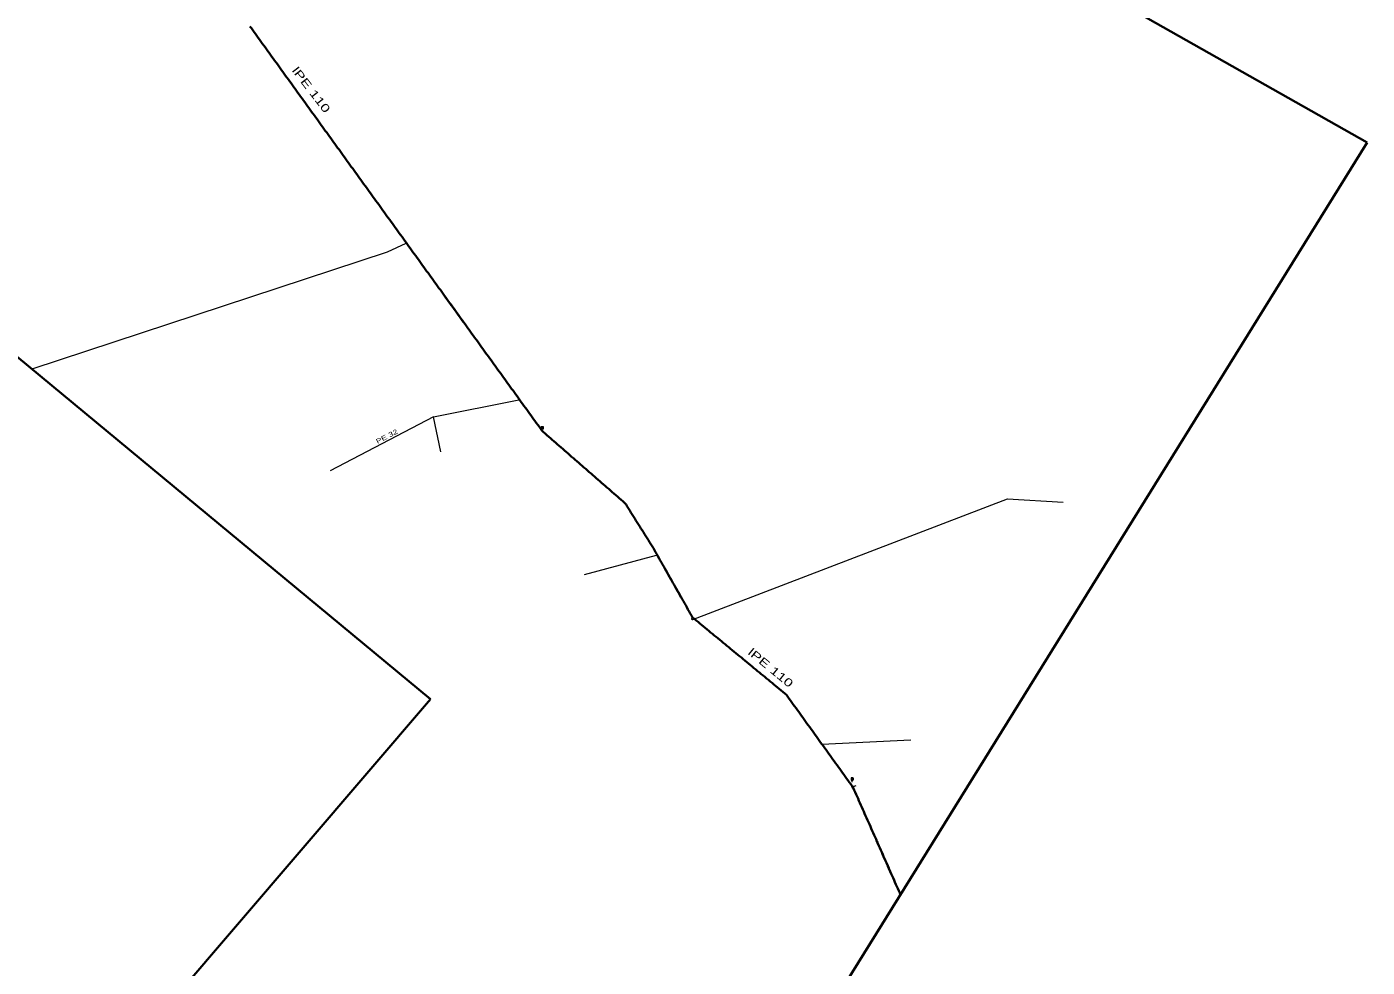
# Model space of a CAD drawing. Extents: x -18.3 to 18.3, y -32.8 to 32.8.
# Drawn here: x 15.245 to 18.281, y 7.625 to 9.754 of the extents above; entities that cross this region are included whole.
import ezdxf

# ---------------------------------------------------------------- set-up
doc = ezdxf.new("R2010")
doc.units = 0
doc.header["$LTSCALE"] = 0.0072
doc.layers.add('16', color=7, linetype='Continuous')
doc.layers.add('18', color=7, linetype='Continuous')
for name, color, linetype, lineweight in [('28', 7, 'Continuous', 13), ('29', 7, 'Continuous', 13), ('5', 7, 'Continuous', 35), ('63', 7, 'Continuous', 35)]:
    doc.layers.add(name, color=color, linetype=linetype, lineweight=lineweight)

msp = doc.modelspace()

# ---------------------------------------------------------------- linework, layer by layer
at = {"layer": '28'}
for p, q in [((16.166365, 8.870458), (15.932656, 8.748563)), ((16.752958, 8.416562), (16.751458, 8.41476)), ((17.045865, 8.12976), (17.247156, 8.139458))]:
    msp.add_line(p, q, dxfattribs=at)
for points in [[(16.105156, 9.263958), (16.10376, 9.263354), (16.061365, 9.243656), (15.256917, 8.978396)], [(16.182865, 8.791458), (16.166365, 8.870458), (16.359656, 8.90926), (16.361156, 8.909562)], [(16.751458, 8.41476), (16.750656, 8.41376), (16.750656, 8.412562), (16.751865, 8.411854), (16.75326, 8.412156), (17.466458, 8.68476), (17.591865, 8.677656)], [(16.508365, 8.513458), (16.67126, 8.557854), (16.672656, 8.55826)], [(17.122656, 8.035063), (17.116958, 8.032958), (17.116458, 8.03176)]]:
    msp.add_lwpolyline(points, dxfattribs=at)
at = {"layer": '29'}
for p, q in [((16.412562, 8.838458), (16.412562, 8.848375)), ((17.114458, 8.043354), (17.114458, 8.053281))]:
    msp.add_line(p, q, dxfattribs=at)
for points in [[(16.410042, 8.848375), (16.410042, 8.8435), (16.415083, 8.8435), (16.415083, 8.848375)], [(16.413031, 8.847906), (16.414615, 8.847906), (16.414615, 8.843969), (16.413031, 8.843969)], [(16.4135, 8.847437), (16.4135, 8.844437), (16.414135, 8.844437), (16.414135, 8.847437)], [(17.111937, 8.053281), (17.111937, 8.048396), (17.116979, 8.048396), (17.116979, 8.053281)], [(17.114927, 8.052812), (17.11651, 8.052812), (17.11651, 8.048865), (17.114927, 8.048865)], [(17.115396, 8.052344), (17.115396, 8.049344), (17.116031, 8.049344), (17.116031, 8.052344)]]:
    msp.add_lwpolyline(points, close=True, dxfattribs=at)
at = {"layer": '5'}
for points in [[(15.750771, 9.754531), (15.753875, 9.75024), (15.756979, 9.745948), (15.760073, 9.741646), (15.763177, 9.737354), (15.766281, 9.733062), (15.769375, 9.728771), (15.772479, 9.724479), (15.775583, 9.720187), (15.778688, 9.715896), (15.781781, 9.711604), (15.784885, 9.707302), (15.78799, 9.70301), (15.791083, 9.698719), (15.794187, 9.694427), (15.797292, 9.690135), (15.800385, 9.685844), (15.80349, 9.681552), (15.806594, 9.67726), (15.809698, 9.672958), (15.812792, 9.668667), (15.815896, 9.664375), (15.819, 9.660083), (15.822094, 9.655792), (15.825198, 9.6515), (15.828302, 9.647208), (15.831406, 9.642917), (15.8345, 9.638615), (15.837604, 9.634323), (15.840708, 9.630031), (15.843802, 9.62574), (15.846906, 9.621448), (15.85001, 9.617156), (15.853115, 9.612865), (15.856208, 9.608573), (15.859312, 9.604271), (15.862417, 9.599979), (15.86551, 9.595688), (15.868615, 9.591396), (15.871719, 9.587104), (15.874823, 9.582812), (15.877917, 9.578521), (15.881021, 9.574229), (15.884125, 9.569927), (15.887219, 9.565635), (15.890323, 9.561344), (15.893427, 9.557052), (15.896521, 9.55276), (15.899625, 9.548469), (15.902729, 9.544177), (15.905833, 9.539885), (15.908927, 9.535583), (15.912031, 9.531292), (15.915135, 9.527), (15.918229, 9.522708), (15.921333, 9.518417), (15.924437, 9.514125), (15.927542, 9.509833), (15.930635, 9.505542), (15.93374, 9.50124), (15.936844, 9.496948), (15.939937, 9.492656), (15.943042, 9.488365), (15.946146, 9.484073), (15.94925, 9.479781), (15.952344, 9.47549), (15.955448, 9.471198), (15.958552, 9.466896), (15.961646, 9.462604), (15.96475, 9.458312), (15.967854, 9.454021), (15.970958, 9.449729), (15.974052, 9.445437), (15.977156, 9.441146), (15.98026, 9.436854), (15.983354, 9.432552), (15.986458, 9.42826), (15.989562, 9.423969), (15.992656, 9.419677), (15.99576, 9.415385), (15.998865, 9.411094), (16.001969, 9.406802), (16.005063, 9.40251), (16.008167, 9.398208), (16.011271, 9.393917), (16.014365, 9.389625), (16.017469, 9.385333)], [(16.017469, 9.385333), (16.020573, 9.381042), (16.023677, 9.37675), (16.026771, 9.372458), (16.029875, 9.368167), (16.032979, 9.363865), (16.036073, 9.359573), (16.039177, 9.355281), (16.042281, 9.35099), (16.045385, 9.346698), (16.048479, 9.342406), (16.051583, 9.338115), (16.054688, 9.333823), (16.057781, 9.329521), (16.060885, 9.325229), (16.06399, 9.320937), (16.067094, 9.316646), (16.070187, 9.312354), (16.073292, 9.308063), (16.076396, 9.303771), (16.07949, 9.299479), (16.082594, 9.295177), (16.085698, 9.290885), (16.088802, 9.286594), (16.091896, 9.282302), (16.095, 9.27801), (16.098104, 9.273719), (16.101198, 9.269427), (16.104302, 9.265135), (16.107406, 9.260833), (16.1105, 9.256542), (16.113604, 9.25225), (16.116708, 9.247958), (16.119812, 9.243667), (16.122906, 9.239375), (16.12601, 9.235083), (16.129115, 9.230792), (16.132208, 9.22649), (16.135312, 9.222198), (16.138417, 9.217906), (16.141521, 9.213615), (16.144615, 9.209323), (16.147719, 9.205031), (16.150823, 9.20074), (16.153917, 9.196448), (16.157021, 9.192146), (16.160125, 9.187854), (16.163229, 9.183562), (16.166323, 9.179271), (16.169427, 9.174979), (16.172531, 9.170687), (16.175625, 9.166396), (16.178729, 9.162104), (16.181833, 9.157802), (16.184938, 9.15351), (16.188031, 9.149219), (16.191135, 9.144927), (16.19424, 9.140635), (16.197333, 9.136344), (16.200437, 9.132052), (16.203542, 9.12776), (16.206635, 9.123458), (16.20974, 9.119167), (16.212844, 9.114875), (16.215948, 9.110583), (16.219042, 9.106292), (16.222146, 9.102), (16.22525, 9.097708), (16.228344, 9.093417), (16.231448, 9.089115), (16.234552, 9.084823)], [(16.188219, 9.148958), (16.191323, 9.144667), (16.194427, 9.140375), (16.197521, 9.136083), (16.200625, 9.131792), (16.203729, 9.1275), (16.206823, 9.123208), (16.209927, 9.118917), (16.213031, 9.114615), (16.216125, 9.110323), (16.219229, 9.106031), (16.222333, 9.10174), (16.225437, 9.097448), (16.228531, 9.093156), (16.231635, 9.088865), (16.23474, 9.084573), (16.237833, 9.080271), (16.240938, 9.075979), (16.244042, 9.071687), (16.247146, 9.067396), (16.25024, 9.063104), (16.253344, 9.058813), (16.256448, 9.054521), (16.259542, 9.050229), (16.262646, 9.045927), (16.26575, 9.041635), (16.268854, 9.037344), (16.271948, 9.033052), (16.275052, 9.02876), (16.278156, 9.024469), (16.28125, 9.020177), (16.284354, 9.015885), (16.287458, 9.011583), (16.290563, 9.007292), (16.293656, 9.003), (16.29676, 8.998708), (16.299865, 8.994417), (16.302958, 8.990125), (16.306062, 8.985833), (16.309167, 8.981542), (16.31226, 8.97724), (16.315365, 8.972948), (16.318469, 8.968656), (16.321573, 8.964365), (16.324667, 8.960073), (16.327771, 8.955781), (16.330875, 8.95149), (16.333969, 8.947198), (16.337073, 8.942896), (16.340177, 8.938604), (16.343281, 8.934312), (16.346375, 8.930021), (16.349479, 8.925729), (16.352583, 8.921437), (16.355677, 8.917146), (16.358781, 8.912854), (16.361885, 8.908563), (16.36499, 8.90426), (16.368094, 8.899969), (16.371187, 8.895677), (16.374292, 8.891385), (16.377396, 8.887094), (16.3805, 8.882802), (16.383604, 8.87851), (16.386708, 8.874219), (16.389812, 8.869927), (16.392906, 8.865635), (16.39601, 8.861344), (16.399115, 8.857052), (16.402219, 8.85276), (16.405323, 8.848469), (16.408427, 8.844177), (16.411531, 8.839885), (16.415229, 8.836135), (16.419219, 8.832656), (16.423208, 8.829187), (16.427208, 8.825708), (16.431198, 8.822229), (16.435198, 8.81875), (16.439187, 8.815271), (16.443177, 8.811792), (16.447177, 8.808312), (16.451167, 8.804833), (16.455167, 8.801365), (16.459156, 8.797885), (16.463146, 8.794406), (16.467146, 8.790927), (16.471135, 8.787448), (16.475135, 8.783969), (16.479125, 8.78049), (16.483125, 8.77701), (16.487115, 8.773542), (16.491104, 8.770062), (16.495104, 8.766583), (16.499094, 8.763104), (16.503094, 8.759625), (16.507083, 8.756146)], [(16.507083, 8.756146), (16.511073, 8.752667), (16.515073, 8.749187), (16.519063, 8.745708), (16.523062, 8.74224), (16.527052, 8.73876), (16.531042, 8.735281), (16.535042, 8.731802), (16.539031, 8.728323), (16.543031, 8.724844), (16.547021, 8.721365), (16.55101, 8.717885), (16.55501, 8.714417), (16.559, 8.710938), (16.563, 8.707458), (16.56699, 8.703979), (16.57099, 8.7005), (16.574979, 8.697021), (16.578969, 8.693542), (16.582969, 8.690062), (16.586958, 8.686594), (16.590958, 8.683115), (16.594948, 8.679635), (16.598937, 8.676156), (16.60226, 8.672104), (16.605073, 8.667615), (16.607885, 8.663125), (16.610698, 8.658646), (16.613521, 8.654156), (16.616333, 8.649667), (16.619146, 8.645177), (16.621958, 8.640698), (16.624771, 8.636208), (16.627583, 8.631719), (16.630396, 8.627229), (16.633208, 8.62275), (16.636021, 8.61826), (16.638833, 8.613771), (16.641646, 8.609281), (16.644458, 8.604802), (16.647271, 8.600312), (16.650083, 8.595823), (16.652896, 8.591333), (16.655719, 8.586854), (16.658531, 8.582365), (16.661344, 8.577875), (16.664135, 8.573375), (16.666729, 8.56876), (16.669333, 8.564156), (16.671937, 8.559542), (16.674542, 8.554927), (16.677156, 8.550323), (16.679771, 8.545719), (16.682375, 8.541104), (16.68499, 8.5365), (16.687604, 8.531896), (16.690208, 8.527281), (16.692823, 8.522677), (16.695438, 8.518073), (16.698042, 8.513458), (16.700656, 8.508854), (16.703271, 8.50425), (16.705875, 8.499635), (16.70849, 8.495031), (16.711104, 8.490427), (16.713708, 8.485823), (16.716323, 8.481208), (16.718937, 8.476604), (16.721542, 8.472), (16.724156, 8.467385), (16.726771, 8.462781)], [(16.68776, 8.531615), (16.690365, 8.52701), (16.692979, 8.522406), (16.695594, 8.517792), (16.698198, 8.513187), (16.700812, 8.508583), (16.703427, 8.503969), (16.706031, 8.499365), (16.708646, 8.49476), (16.71126, 8.490146), (16.713865, 8.485542), (16.716479, 8.480937), (16.719094, 8.476323), (16.721698, 8.471719), (16.724312, 8.467115), (16.726927, 8.4625), (16.729531, 8.457896), (16.732146, 8.453292), (16.73476, 8.448677), (16.737365, 8.444073), (16.739979, 8.439469), (16.742594, 8.434854), (16.745198, 8.43025), (16.747812, 8.425646), (16.750427, 8.421031), (16.753073, 8.416469), (16.757167, 8.413094), (16.76125, 8.409729), (16.765333, 8.406365), (16.769427, 8.40299), (16.77351, 8.399625), (16.777604, 8.39626), (16.781688, 8.392896), (16.785771, 8.389521), (16.789865, 8.386156), (16.793948, 8.382792), (16.798042, 8.379427), (16.802125, 8.376052), (16.806208, 8.372687), (16.810302, 8.369323), (16.814385, 8.365948), (16.818479, 8.362583), (16.822563, 8.359219), (16.826646, 8.355854), (16.83074, 8.352479), (16.834823, 8.349115), (16.838917, 8.34575), (16.843, 8.342385), (16.847083, 8.33901), (16.851177, 8.335646), (16.85526, 8.332281), (16.859354, 8.328917), (16.863437, 8.325542), (16.867521, 8.322177), (16.871615, 8.318812), (16.875698, 8.315437), (16.879792, 8.312073), (16.883875, 8.308708), (16.887958, 8.305344), (16.892052, 8.301969), (16.896135, 8.298604), (16.900229, 8.29524), (16.904312, 8.291875), (16.908396, 8.2885), (16.91249, 8.285135), (16.916573, 8.281771), (16.920667, 8.278396), (16.92475, 8.275031), (16.928833, 8.271667), (16.932927, 8.268302), (16.93701, 8.264927), (16.941094, 8.261563), (16.945187, 8.258198), (16.949271, 8.254833), (16.953365, 8.251458), (16.957448, 8.248094), (16.961531, 8.244729), (16.965531, 8.241281), (16.968635, 8.236979), (16.971729, 8.232687), (16.974823, 8.228385), (16.977917, 8.224083), (16.98101, 8.219792), (16.984104, 8.21549), (16.987198, 8.211198), (16.990302, 8.206896), (16.993396, 8.202604), (16.99649, 8.198302), (16.999583, 8.19401), (17.002677, 8.189708), (17.005771, 8.185417), (17.008865, 8.181115), (17.011969, 8.176823), (17.015062, 8.172521), (17.018156, 8.168229), (17.02125, 8.163927), (17.024344, 8.159625)], [(17.024344, 8.159625), (17.027437, 8.155333), (17.030531, 8.151031), (17.033635, 8.14674), (17.036729, 8.142437), (17.039823, 8.138146), (17.042917, 8.133844), (17.04601, 8.129552), (17.049104, 8.12525), (17.052198, 8.120958), (17.055302, 8.116656), (17.058396, 8.112365), (17.06149, 8.108062), (17.064583, 8.103771), (17.067677, 8.099469), (17.070781, 8.095177), (17.073875, 8.090875), (17.076969, 8.086583), (17.080063, 8.082281), (17.083156, 8.07799), (17.08625, 8.073688), (17.089354, 8.069396), (17.092448, 8.065094), (17.095542, 8.060802), (17.098635, 8.0565), (17.101729, 8.052208), (17.104823, 8.047906), (17.107927, 8.043604), (17.111021, 8.039312), (17.114115, 8.03501), (17.116979, 8.030583), (17.119125, 8.02574), (17.12126, 8.020896), (17.123406, 8.016052), (17.125542, 8.011208), (17.127688, 8.006365), (17.129833, 8.001521), (17.131969, 7.996677), (17.134115, 7.991833), (17.13625, 7.98699), (17.138396, 7.982146), (17.140542, 7.977313), (17.142677, 7.972469), (17.144823, 7.967625), (17.146958, 7.962781), (17.149104, 7.957937), (17.15125, 7.953094), (17.153385, 7.94825), (17.155531, 7.943406), (17.157677, 7.938562), (17.159813, 7.933719), (17.161958, 7.928875), (17.164094, 7.924031), (17.16624, 7.919187), (17.168385, 7.914344), (17.170521, 7.9095), (17.172667, 7.904656), (17.174802, 7.899812), (17.176948, 7.894969), (17.179094, 7.890125), (17.181229, 7.885281), (17.183375, 7.880437), (17.18551, 7.875594), (17.187656, 7.87075), (17.189802, 7.865906), (17.191937, 7.861063), (17.194083, 7.856219), (17.196219, 7.851375), (17.198365, 7.846531), (17.20051, 7.841687), (17.202646, 7.836844)], [(17.170646, 7.909208), (17.172792, 7.904365), (17.174937, 7.899521), (17.177073, 7.894677), (17.179219, 7.889833), (17.181365, 7.88499), (17.1835, 7.880146), (17.185646, 7.875302), (17.187781, 7.870458), (17.189927, 7.865615), (17.192073, 7.860771), (17.194208, 7.855927), (17.196354, 7.851083), (17.19849, 7.84624), (17.200635, 7.841396), (17.202781, 7.836552), (17.204917, 7.831708), (17.207062, 7.826865), (17.209198, 7.822021), (17.211344, 7.817177), (17.21349, 7.812333), (17.215625, 7.80749), (17.217771, 7.802646), (17.219906, 7.797802), (17.222052, 7.792958), (17.223823, 7.788958)]]:
    msp.add_lwpolyline(points, dxfattribs=at)
at = {"layer": '63'}
msp.add_lwpolyline([(6.821417, -12.034073), (10.570802, 1.718333), (16.15951, 8.231344), (14.281458, 9.78576), (7.75526, 16.244156), (2.207979, 21.642292), (-4.211323, 25.162208), (-9.541, 28.856333), (-11.476635, 29.828458), (-11.428635, 28.932656), (-12.590438, 28.732062), (-18.280635, 29.748156), (-18.02001, 32.23425), (-12.039885, 32.814354), (-8.624021, 29.362521), (-2.888135, 26.135219), (2.67676, 22.377854), (8.287094, 17.445521), (15.252958, 11.204562), (18.280635, 9.491437), (12.985292, 0.960906), (8.539271, -13.360323)], dxfattribs=at)

# ---------------------------------------------------------------- texts
at = {"layer": '16', "width": 1.45}
for rotation, p in [(307.57, (15.844719, 9.654208)), (320.517, (16.876656, 8.334698))]:
    msp.add_text('lPE 110', height=0.01812, rotation=rotation, dxfattribs=at).set_placement(p)
at = {"layer": '18', "width": 1.35}
msp.add_text('PE 32', height=0.01087, rotation=27.547, dxfattribs=at).set_placement((16.039521, 8.809292))

doc.saveas('drawing.dxf')
